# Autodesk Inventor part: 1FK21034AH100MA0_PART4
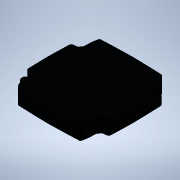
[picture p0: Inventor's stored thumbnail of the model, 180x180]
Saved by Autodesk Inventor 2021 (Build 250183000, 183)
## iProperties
Created: 2025-04
Part Number: 1FK21034AH100MA0_PART4
Material: Generic
Catalog Web Link: www.3dfindit.com
Description: -Servo synchronous motor
Document SubType Name: Modeling
Designer: psAdmin
Mass: 37.514 g
Surface Area: 101.697 cm^2
Volume: 37.514 cm^3
Density: 1 g/cm^3
Appearance: PSOLRGB-38-46-56
Category: PARTsolutions
Title: 1FK21034AH100MA0_PART4
Author: Cadenas PARTsolutions
Comments: Servo synchronous motor
Sending System: PARTsolutions
Preprocessor: ST-DEVELOPER v19.3
PSOL_IDENT_0: {$CADENAS_DATA/23d-libs/siemens_ag/_cat_/39/97/1fk21034ah100ma0.prj},213 {VTYP=3D},{NB=1FK21034AH100
PSOL_IDENT_1: MA0_PART4},{LINA=1FK21034AH100MA0_PART4},{NN=1FK21034AH100MA0_PART4},{NOPRJ=TRUE},{DATE=19.08.2025 1
PSOL_IDENT_2: 4:00:33},{GEOMDATE=30.07.2025 02:02:21},{VERSION=},{LINEID=10},{WBVAR=},{WBNUMERIC=}  {NB=1FK21034AH
PSOL_IDENT_3: 100MA0_PART4},{LINA=1FK21034AH100MA0_PART4},{KT=DUMMY},{PREVIEW=../../../_pool_/d3/78/p_d211_xx_0093
PSOL_IDENT_4: 4j.png},{DESCSHORT=SIMOTICS S-1FK2 HD, SINAMICS S210 3AC 400V-480V, 1.01 Nm, 4500 rpm},{DESCLONG=SIM
PSOL_IDENT_5: OTICS S-1FK2 HD servo motor M0=1.27 Nm; PN = 0.48 kW at nN=4500 rpm (380-480 V); PN = 0.3 kW at nN=2
PSOL_IDENT_6: 500 rpm (200-240 V); with holding brake; degree of protection IP64; cylindrical shaft D14 x 30 mm; a
PSOL_IDENT_7: bsolute encoder 22-bit + 12-bit multiturn (encoder AM22DQC); with OCC interface; plug size M17, rota
PSOL_IDENT_8: table; SIMOTICS S-1FK2 servomotorfor a wide range of uses in industrial environments. SIMOTICS S‑1FK
PSOL_IDENT_9: 2 servomotors are compact synchronous motors with a high dynamic performance that set themselves apa
PSOL_IDENT_10: rt as a result of their high power density, degree of protection and overload capability. The motors
PSOL_IDENT_11: are available in two variants: as High Dynamic variant (highest dynamic performance as a result of
PSOL_IDENT_12: the low intrinsic moment of inertia for applications demanding a high dynamic performance with low m
PSOL_IDENT_13: oved masses) - and as Compact variant (precise and stable closed-loop control for medium up to large
PSOL_IDENT_14: moved masses as a result of a medium intrinsic moment of inertia). SIMOTICSS‑1FK2 servomotors fully
PSOL_IDENT_15: exploit their strengths in a system with the SINAMICSS210 frequency converter and simple connection
PSOL_IDENT_16: using the one cable connection (OCC). Advantages include the short control and positioning times, f
PSOL_IDENT_17: ast and precise correction of disturbing quantities as well as stable control with a high dynamic pe
PSOL_IDENT_18: rformance. The servo motors can be configured to address a wide range of requirements. For example w
PSOL_IDENT_19: ith and without holding brake, IP64 or IP65 degree of protection, singleturn or multiturn absolute e
PSOL_IDENT_20: ncoders - to name just a few. Further, the servomotors are available in different shaft heights exte
PSOL_IDENT_21: nding from 20 to 100. A shaft sealing ring is available to achieve an IP65 degree of protection and
PSOL_IDENT_22: for subsequent mounting at the motor or as spare part. SIMOTICS - the optimum motor for each and eve
PSOL_IDENT_23: ry motion control application.},{INTNO=195125454019},{SUPPLIERALTNO=1FK2103-4AH10-0MA0},{MANUID=1FK2
PSOL_IDENT_24: 1034AH100MA0},{MANUNAME=Siemens},{MANUTYPEDESC=SYNCHRONOUS MOTOR 1FK2 HD 1,27 NM},{AAU732=SIMOTICS},
PSOL_IDENT_25: {AAO057=S-1FK2},{AAU734=SIMOTICS S-1FK2 HD servo motor M0=1.27 Nm; PN = 0.48 kW at nN=4500 rpm (380-
PSOL_IDENT_26: 480 V); PN = 0.3 kW at nN=2500 rpm (200-240 V); with holding brake; degree of protection IP64; cylin
PSOL_IDENT_27: drical shaft D14 x 30 mm; absolute encoder 22-bit + 12-bit multiturn (encoder AM22DQC); with OCC int
PSOL_IDENT_28: erface; plug size M17, rotatable;},{AAW338=SYNCHRONOUS MOTOR 1FK2 HD 1,27 NM},{AAO742=SIMOTICS},{AAO
PSOL_IDENT_29: 663=4034106444921},{NOCUPEROU=1},{PRICEQUANTITY=1},{QUANTITYMIN=1},{QUANTITYINT=1},{CTN=85015100},{C
PSOL_IDENT_30: OO=RO},{AAO676=1FK2103-4AH10-0MA0},{AAO677=Siemens AG},{ORDERUNIT=C62},{CONTENTUNIT=C62}
NB: 1FK21034AH100MA0_PART4
NT: Servo synchronous motor
NBSYN: $MANUID._PART4
LINA: 1FK21034AH100MA0_PART4
CATALOG: SIEMENS
PREVIEW: ../../../_pool_/d3/78/p_d211_xx_00934j.png
DESCSHORT: SIMOTICS S-1FK2 HD, SINAMICS S210 3AC 400V-480V, 1.01 Nm, 4500 rpm
DESCLONG: SIMOTICS S-1FK2 HD servo motor M0=1.27 Nm; PN = 0.48 kW at nN=4500 rpm (380-480 V); PN = 0.3 kW at nN=2500 rpm (200-240 V); with holding brake; degree of protec
INTNO: 195125454019
SUPPLIERALTNO: 1FK2103-4AH10-0MA0
MANUID: 1FK21034AH100MA0
MANUNAME: Siemens
MANUTYPEDESC: SYNCHRONOUS MOTOR 1FK2 HD 1,27 NM
AAU732: SIMOTICS
AAO057: S-1FK2
AAU734: SIMOTICS S-1FK2 HD servo motor M0=1.27 Nm; PN = 0.48 kW at nN=4500 rpm (380-480 V); PN = 0.3 kW at nN=2500 rpm (200-240 V); with holding brake; degree of protec
AAW338: SYNCHRONOUS MOTOR 1FK2 HD 1,27 NM
AAO742: SIMOTICS
AAO663: 4034106444921.0
NOCUPEROU: 1
PRICEQUANTITY: 1
QUANTITYMIN: 1
QUANTITYINT: 1
CTN: 85015100
COO: RO
ARTICLENO: 1FK21034AH100MA0_PART4
BOMINFO: 1FK21034AH100MA0_PART4
CREATOR: CADENAS GmbH
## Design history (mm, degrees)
feature "2025_04_17_15_09_00_0268"
body "Solid1"
